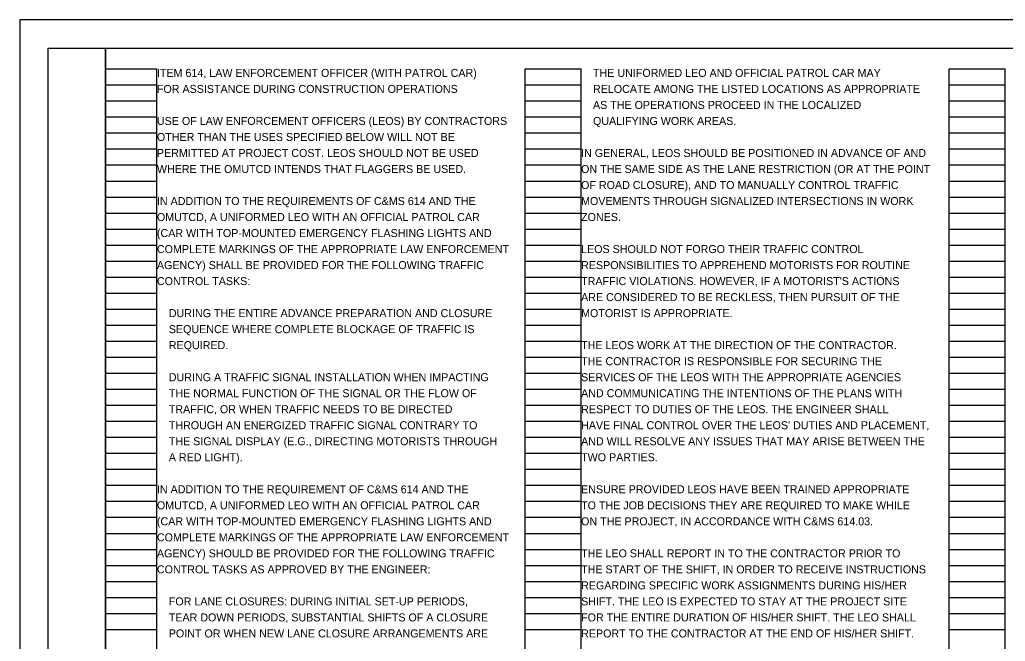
# Model space of a CAD drawing. Extents: x 0 to 86.6, y -18.4 to 22.
# Drawn here: x 0 to 17.24, y 11.13 to 22 of the extents above; entities that cross this region are included whole.
import ezdxf

# ---------------------------------------------------------------- set-up
doc = ezdxf.new("R2010")
doc.units = 0
for name, color, linetype in [('SH_Border', 7, 'Continuous'), ('SH_Cut_Line', 7, 'Continuous'), ('SH_Data', 7, 'Continuous'), ('SH_Text', 7, 'Continuous')]:
    doc.layers.add(name, color=color, linetype=linetype)

msp = doc.modelspace()

# ---------------------------------------------------------------- linework, layer by layer
at = {"layer": 'SH_Border'}
for points in [[(0.5, 21.5), (1.5, 21.5), (1.5, 0.5), (0.5, 0.5)], [(1.5, 21.5), (33.5, 21.5), (33.5, 0.5), (1.5, 0.5)]]:
    msp.add_lwpolyline(points, close=True, dxfattribs=at)
at = {"layer": 'SH_Cut_Line'}
msp.add_lwpolyline([(0, 0), (34, 0), (34, 22), (0, 22)], close=True, dxfattribs=at)
at = {"layer": 'SH_Data'}
for p, q in [((1.5, 0.98), (1.5, 21.14)), ((1.5, 21.14), (2.4, 21.14)), ((2.4, 0.98), (2.4, 21.14)), ((8.84, 0.98), (8.84, 21.14)), ((8.84, 21.14), (9.82, 21.14)), ((9.82, 0.98), (9.82, 21.14)), ((16.26, 0.98), (16.26, 21.14)), ((16.26, 21.14), (17.24, 21.14)), ((17.24, 0.98), (17.24, 21.14)), ((1.5, 20.86), (2.4, 20.86)), ((8.84, 20.86), (9.82, 20.86)), ((16.26, 20.86), (17.24, 20.86)), ((1.5, 20.58), (2.4, 20.58)), ((8.84, 20.58), (9.82, 20.58)), ((16.26, 20.58), (17.24, 20.58)), ((1.5, 20.3), (2.4, 20.3)), ((8.84, 20.3), (9.82, 20.3)), ((16.26, 20.3), (17.24, 20.3)), ((1.5, 20.02), (2.4, 20.02)), ((8.84, 20.02), (9.82, 20.02)), ((16.26, 20.02), (17.24, 20.02)), ((1.5, 19.74), (2.4, 19.74)), ((8.84, 19.74), (9.82, 19.74)), ((16.26, 19.74), (17.24, 19.74)), ((1.5, 19.46), (2.4, 19.46)), ((8.84, 19.46), (9.82, 19.46)), ((16.26, 19.46), (17.24, 19.46)), ((1.5, 19.18), (2.4, 19.18)), ((8.84, 19.18), (9.82, 19.18)), ((16.26, 19.18), (17.24, 19.18)), ((1.5, 18.9), (2.4, 18.9)), ((8.84, 18.9), (9.82, 18.9)), ((16.26, 18.9), (17.24, 18.9)), ((1.5, 18.62), (2.4, 18.62)), ((8.84, 18.62), (9.82, 18.62)), ((16.26, 18.62), (17.24, 18.62)), ((1.5, 18.34), (2.4, 18.34)), ((8.84, 18.34), (9.82, 18.34)), ((16.26, 18.34), (17.24, 18.34)), ((1.5, 18.06), (2.4, 18.06)), ((8.84, 18.06), (9.82, 18.06)), ((16.26, 18.06), (17.24, 18.06)), ((1.5, 17.78), (2.4, 17.78)), ((8.84, 17.78), (9.82, 17.78)), ((16.26, 17.78), (17.24, 17.78)), ((1.5, 17.5), (2.4, 17.5)), ((8.84, 17.5), (9.82, 17.5)), ((16.26, 17.5), (17.24, 17.5)), ((1.5, 17.22), (2.4, 17.22)), ((8.84, 17.22), (9.82, 17.22)), ((16.26, 17.22), (17.24, 17.22)), ((1.5, 16.94), (2.4, 16.94)), ((8.84, 16.94), (9.82, 16.94)), ((16.26, 16.94), (17.24, 16.94)), ((1.5, 16.66), (2.4, 16.66)), ((8.84, 16.66), (9.82, 16.66)), ((16.26, 16.66), (17.24, 16.66)), ((1.5, 16.38), (2.4, 16.38)), ((8.84, 16.38), (9.82, 16.38)), ((16.26, 16.38), (17.24, 16.38)), ((1.5, 16.1), (2.4, 16.1)), ((8.84, 16.1), (9.82, 16.1)), ((16.26, 16.1), (17.24, 16.1)), ((1.5, 15.82), (2.4, 15.82)), ((8.84, 15.82), (9.82, 15.82)), ((16.26, 15.82), (17.24, 15.82)), ((1.5, 15.54), (2.4, 15.54)), ((8.84, 15.54), (9.82, 15.54)), ((16.26, 15.54), (17.24, 15.54)), ((1.5, 15.26), (2.4, 15.26)), ((8.84, 15.26), (9.82, 15.26)), ((16.26, 15.26), (17.24, 15.26)), ((1.5, 14.98), (2.4, 14.98)), ((8.84, 14.98), (9.82, 14.98)), ((16.26, 14.98), (17.24, 14.98)), ((1.5, 14.7), (2.4, 14.7)), ((8.84, 14.7), (9.82, 14.7)), ((16.26, 14.7), (17.24, 14.7)), ((1.5, 14.42), (2.4, 14.42)), ((8.84, 14.42), (9.82, 14.42)), ((16.26, 14.42), (17.24, 14.42)), ((1.5, 14.14), (2.4, 14.14)), ((8.84, 14.14), (9.82, 14.14)), ((16.26, 14.14), (17.24, 14.14)), ((1.5, 13.86), (2.4, 13.86)), ((8.84, 13.86), (9.82, 13.86)), ((16.26, 13.86), (17.24, 13.86)), ((1.5, 13.58), (2.4, 13.58)), ((8.84, 13.58), (9.82, 13.58)), ((16.26, 13.58), (17.24, 13.58)), ((1.5, 13.3), (2.4, 13.3)), ((8.84, 13.3), (9.82, 13.3)), ((16.26, 13.3), (17.24, 13.3)), ((1.5, 13.02), (2.4, 13.02)), ((8.84, 13.02), (9.82, 13.02)), ((16.26, 13.02), (17.24, 13.02)), ((1.5, 12.74), (2.4, 12.74)), ((8.84, 12.74), (9.82, 12.74)), ((16.26, 12.74), (17.24, 12.74)), ((1.5, 12.46), (2.4, 12.46)), ((8.84, 12.46), (9.82, 12.46)), ((16.26, 12.46), (17.24, 12.46)), ((1.5, 12.18), (2.4, 12.18)), ((8.84, 12.18), (9.82, 12.18)), ((16.26, 12.18), (17.24, 12.18)), ((1.5, 11.9), (2.4, 11.9)), ((8.84, 11.9), (9.82, 11.9)), ((16.26, 11.9), (17.24, 11.9)), ((1.5, 11.62), (2.4, 11.62)), ((8.84, 11.62), (9.82, 11.62)), ((16.26, 11.62), (17.24, 11.62)), ((1.5, 11.34), (2.4, 11.34)), ((8.84, 11.34), (9.82, 11.34)), ((16.26, 11.34), (17.24, 11.34))]:
    msp.add_line(p, q, dxfattribs=at)

# ---------------------------------------------------------------- texts
at = {"layer": 'SH_Text'}
for s, p in [('ITEM 614, LAW ENFORCEMENT OFFICER (WITH PATROL CAR)', (2.4, 21)), ('    THE UNIFORMED LEO AND OFFICIAL PATROL CAR MAY', (9.82, 21)), ('FOR ASSISTANCE DURING CONSTRUCTION OPERATIONS', (2.4, 20.72)), ('    RELOCATE AMONG THE LISTED LOCATIONS AS APPROPRIATE', (9.82, 20.72)), ('    AS THE OPERATIONS PROCEED IN THE LOCALIZED', (9.82, 20.44)), ('USE OF LAW ENFORCEMENT OFFICERS (LEOS) BY CONTRACTORS', (2.4, 20.16)), ('    QUALIFYING WORK AREAS.', (9.82, 20.16)), ('OTHER THAN THE USES SPECIFIED BELOW WILL NOT BE', (2.4, 19.88)), ('PERMITTED AT PROJECT COST. LEOS SHOULD NOT BE USED', (2.4, 19.6)), ('IN GENERAL, LEOS SHOULD BE POSITIONED IN ADVANCE OF AND', (9.82, 19.6)), ('WHERE THE OMUTCD INTENDS THAT FLAGGERS BE USED.', (2.4, 19.32)), ('ON THE SAME SIDE AS THE LANE RESTRICTION (OR AT THE POINT', (9.82, 19.32)), ('OF ROAD CLOSURE), AND TO MANUALLY CONTROL TRAFFIC', (9.82, 19.04)), ('IN ADDITION TO THE REQUIREMENTS OF C&MS 614 AND THE', (2.4, 18.76)), ('MOVEMENTS THROUGH SIGNALIZED INTERSECTIONS IN WORK', (9.82, 18.76)), ('OMUTCD, A UNIFORMED LEO WITH AN OFFICIAL PATROL CAR', (2.4, 18.48)), ('ZONES.', (9.82, 18.48)), ('(CAR WITH TOP-MOUNTED EMERGENCY FLASHING LIGHTS AND', (2.4, 18.2)), ('COMPLETE MARKINGS OF THE APPROPRIATE LAW ENFORCEMENT', (2.4, 17.92)), ('LEOS SHOULD NOT FORGO THEIR TRAFFIC CONTROL', (9.82, 17.92)), ('AGENCY) SHALL BE PROVIDED FOR THE FOLLOWING TRAFFIC', (2.4, 17.64)), ('RESPONSIBILITIES TO APPREHEND MOTORISTS FOR ROUTINE', (9.82, 17.64)), ('CONTROL TASKS:', (2.4, 17.36)), ("TRAFFIC VIOLATIONS. HOWEVER, IF A MOTORIST'S ACTIONS", (9.82, 17.36)), ('ARE CONSIDERED TO BE RECKLESS, THEN PURSUIT OF THE', (9.82, 17.08)), ('    DURING THE ENTIRE ADVANCE PREPARATION AND CLOSURE', (2.4, 16.8)), ('MOTORIST IS APPROPRIATE.', (9.82, 16.8)), ('    SEQUENCE WHERE COMPLETE BLOCKAGE OF TRAFFIC IS', (2.4, 16.52)), ('    REQUIRED.', (2.4, 16.24)), ('THE LEOS WORK AT THE DIRECTION OF THE CONTRACTOR.', (9.82, 16.24)), ('THE CONTRACTOR IS RESPONSIBLE FOR SECURING THE', (9.82, 15.96)), ('    DURING A TRAFFIC SIGNAL INSTALLATION WHEN IMPACTING', (2.4, 15.68)), ('SERVICES OF THE LEOS WITH THE APPROPRIATE AGENCIES', (9.82, 15.68)), ('    THE NORMAL FUNCTION OF THE SIGNAL OR THE FLOW OF', (2.4, 15.4)), ('AND COMMUNICATING THE INTENTIONS OF THE PLANS WITH', (9.82, 15.4)), ('    TRAFFIC, OR WHEN TRAFFIC NEEDS TO BE DIRECTED', (2.4, 15.12)), ('RESPECT TO DUTIES OF THE LEOS. THE ENGINEER SHALL', (9.82, 15.12)), ('    THROUGH AN ENERGIZED TRAFFIC SIGNAL CONTRARY TO', (2.4, 14.84)), ("HAVE FINAL CONTROL OVER THE LEOS' DUTIES AND PLACEMENT,", (9.82, 14.84)), ('    THE SIGNAL DISPLAY (E.G., DIRECTING MOTORISTS THROUGH', (2.4, 14.56)), ('AND WILL RESOLVE ANY ISSUES THAT MAY ARISE BETWEEN THE', (9.82, 14.56)), ('    A RED LIGHT).', (2.4, 14.28)), ('TWO PARTIES.', (9.82, 14.28)), ('IN ADDITION TO THE REQUIREMENT OF C&MS 614 AND THE', (2.4, 13.72)), ('ENSURE PROVIDED LEOS HAVE BEEN TRAINED APPROPRIATE', (9.82, 13.72)), ('OMUTCD, A UNIFORMED LEO WITH AN OFFICIAL PATROL CAR', (2.4, 13.44)), ('TO THE JOB DECISIONS THEY ARE REQUIRED TO MAKE WHILE', (9.82, 13.44)), ('(CAR WITH TOP-MOUNTED EMERGENCY FLASHING LIGHTS AND', (2.4, 13.16)), ('ON THE PROJECT, IN ACCORDANCE WITH C&MS 614.03.', (9.82, 13.16)), ('COMPLETE MARKINGS OF THE APPROPRIATE LAW ENFORCEMENT', (2.4, 12.88)), ('AGENCY) SHOULD BE PROVIDED FOR THE FOLLOWING TRAFFIC', (2.4, 12.6)), ('THE LEO SHALL REPORT IN TO THE CONTRACTOR PRIOR TO', (9.82, 12.6)), ('CONTROL TASKS AS APPROVED BY THE ENGINEER:', (2.4, 12.32)), ('THE START OF THE SHIFT, IN ORDER TO RECEIVE INSTRUCTIONS', (9.82, 12.32)), ('REGARDING SPECIFIC WORK ASSIGNMENTS DURING HIS/HER', (9.82, 12.04)), ('    FOR LANE CLOSURES: DURING INITIAL SET-UP PERIODS,', (2.4, 11.76)), ('SHIFT. THE LEO IS EXPECTED TO STAY AT THE PROJECT SITE', (9.82, 11.76)), ('    TEAR DOWN PERIODS, SUBSTANTIAL SHIFTS OF A CLOSURE', (2.4, 11.48)), ('FOR THE ENTIRE DURATION OF HIS/HER SHIFT. THE LEO SHALL', (9.82, 11.48)), ('    POINT OR WHEN NEW LANE CLOSURE ARRANGEMENTS ARE', (2.4, 11.2)), ('REPORT TO THE CONTRACTOR AT THE END OF HIS/HER SHIFT.', (9.82, 11.2))]:
    msp.add_text(s, height=0.14, dxfattribs=at).set_placement(p)

doc.saveas('drawing.dxf')
